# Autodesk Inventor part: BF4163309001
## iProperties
Shininess: 64.0
Angle Display Precision: 2
Document Length Units: 11272
Document Angle Units: 11279
Document Time Units: 11290
Document Mass Units: 11286
Document Length Units Precision: 3
Document Angle Units Precision: 2
Created: 2003-05
Part Number: BF4163309001
Material: Bronze, Soft Tin
Description: 1/8 x 0.75 NIPPLE, SCH 40, RED BRASS, TBE
Vendor: BF4163309001
Document SubType Name: Modeling
Designer: RCOPE
Density: 8.874
Volumn: 0.8054624159511496
Area: 10.77729494780468
PropertySet Name: Model Information
Control State: 0
Master: False
Checked Out: False
Title: NIPPLE, SCH 40, RED BRASS, TBE
Author: RCOPE
Revision Number: 0
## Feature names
1. Extrusion1
2. Extrusion2
3. Extrusion3
4. Extrusion4
